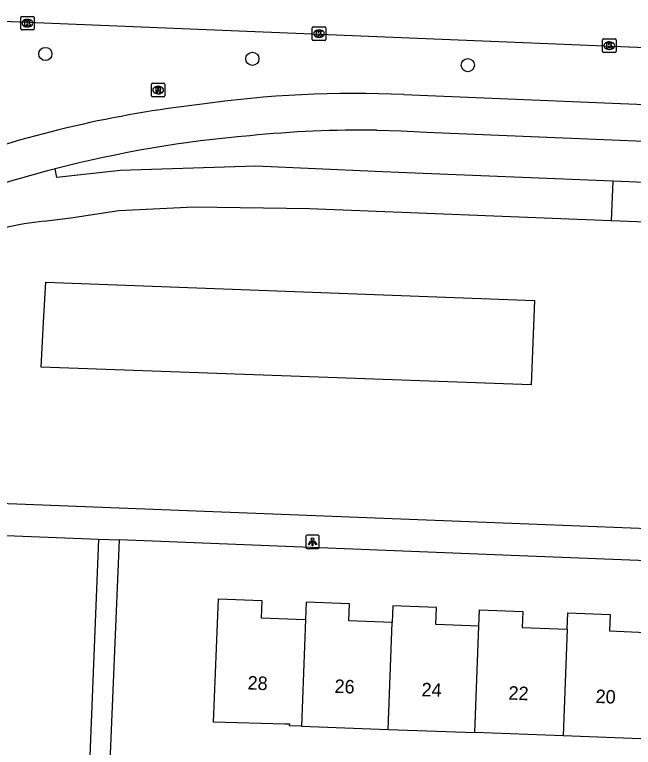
# Model space of a CAD drawing. Extents: x 161355 to 162026, y 386504 to 387459.
# Drawn here: x 161584 to 161629.9, y 387396.4 to 387450.8 of the extents above; entities that cross this region are included whole.
import ezdxf

# ---------------------------------------------------------------- set-up
doc = ezdxf.new("R2010")
doc.units = 0
for name, color, linetype in [('IMGEO_Boom', 7, 'Continuous'), ('IMGEO_Fietspad_gesloten', 7, 'Continuous'), ('IMGEO_Groenvoorziening', 7, 'Continuous'), ('IMGEO_Kolk', 7, 'Continuous'), ('IMGEO_Lichtpunt', 7, 'Continuous'), ('IMGEO_Pand', 7, 'Continuous'), ('IMGEO_Pand_nummerreeks', 7, 'Continuous'), ('IMGEO_Rijbaan_lokaal_gesloten', 7, 'Continuous'), ('IMGEO_Rioolput', 7, 'Continuous'), ('IMGEO_Voetpad_open', 7, 'Continuous')]:
    doc.layers.add(name, color=color, linetype=linetype)

msp = doc.modelspace()

# ---------------------------------------------------------------- linework, layer by layer
at = {"layer": 'IMGEO_Boom'}
for centre in [(161586.274, 387447.924), (161601.637, 387447.563), (161617.626, 387447.099)]:
    msp.add_circle(centre, 0.489, dxfattribs=at)
at = {"layer": 'IMGEO_Fietspad_gesloten'}
for points in [[(161612.89, 387444.91), (161652.822, 387443.267), (161706.244, 387441.015), (161723.243, 387440.365), (161738.753, 387439.947)], [(161610.883, 387442.256), (161612.683, 387442.214), (161614.558, 387442.129), (161644.429, 387440.874), (161676.294, 387439.535), (161679.83, 387439.386), (161708.067, 387438.213), (161738.649, 387436.943)], [(161586.996, 387439.386), (161586.923, 387439.367)]]:
    msp.add_lwpolyline(points, dxfattribs=at)
for centre, radius, start, end in [((161609.251, 387362.569), 82.421, 87.46975, 98.04602), ((161607.624, 387359.522), 85.235, 96.67591, 109.35439), ((161608.735, 387355.708), 86.455, 94.83564, 104.56317), ((161609.758, 387357.301), 84.963, 89.24122, 95.61351), ((161611.973, 387342.556), 100, 104.50687, 109.09324)]:
    msp.add_arc(centre, radius, start, end, dxfattribs=at)
at = {"layer": 'IMGEO_Groenvoorziening'}
msp.add_lwpolyline([(161622.32, 387423.351), (161585.965, 387424.664), (161586.147, 387428.006), (161586.309, 387430.965), (161622.577, 387429.606), (161622.32, 387423.351)], dxfattribs=at)
at = {"layer": 'IMGEO_Kolk'}
for p, q in [((161584.44, 387449.785), (161584.44, 387450.637)), ((161584.515, 387450.711), (161585.367, 387450.711)), ((161584.928, 387450.491), (161584.953, 387450.491)), ((161585.441, 387450.637), (161585.441, 387449.785)), ((161584.951, 387449.931), (161584.926, 387449.931)), ((161606.162, 387449.934), (161607.014, 387449.934)), ((161585.367, 387449.711), (161584.515, 387449.711)), ((161606.087, 387449.008), (161606.087, 387449.86)), ((161606.575, 387449.714), (161606.6, 387449.714)), ((161607.088, 387449.86), (161607.088, 387449.008)), ((161607.014, 387448.934), (161606.162, 387448.934)), ((161606.598, 387449.154), (161606.573, 387449.154)), ((161627.634, 387448.118), (161627.634, 387448.97)), ((161627.709, 387449.044), (161628.561, 387449.044)), ((161628.635, 387448.97), (161628.635, 387448.118)), ((161628.122, 387448.824), (161628.147, 387448.824)), ((161628.561, 387448.044), (161627.709, 387448.044)), ((161628.145, 387448.264), (161628.12, 387448.264))]:
    msp.add_line(p, q, dxfattribs=at)
for points in [[(161584.44, 387449.785), (161584.44, 387450.637)], [(161584.515, 387450.711), (161585.367, 387450.711)], [(161585.441, 387450.637), (161585.441, 387449.785)], [(161584.761, 387450.411), (161584.884, 387450.411), (161584.884, 387450.26), (161585.014, 387450.411), (161585.178, 387450.411), (161585.032, 387450.26), (161585.185, 387450.011), (161585.033, 387450.011), (161584.948, 387450.175), (161584.884, 387450.108), (161584.884, 387450.011), (161584.761, 387450.011), (161584.761, 387450.411)], [(161606.162, 387449.934), (161607.014, 387449.934)], [(161585.367, 387449.711), (161584.515, 387449.711)], [(161606.087, 387449.008), (161606.087, 387449.86)], [(161606.408, 387449.634), (161606.531, 387449.634), (161606.531, 387449.483), (161606.661, 387449.634), (161606.825, 387449.634), (161606.679, 387449.483), (161606.832, 387449.234), (161606.68, 387449.234), (161606.595, 387449.398), (161606.531, 387449.331), (161606.531, 387449.234), (161606.408, 387449.234), (161606.408, 387449.634)], [(161607.088, 387449.86), (161607.088, 387449.008)], [(161607.014, 387448.934), (161606.162, 387448.934)], [(161627.634, 387448.118), (161627.634, 387448.97)], [(161627.709, 387449.044), (161628.561, 387449.044)], [(161628.635, 387448.97), (161628.635, 387448.118)], [(161627.955, 387448.744), (161628.078, 387448.744), (161628.078, 387448.593), (161628.208, 387448.744), (161628.372, 387448.744), (161628.226, 387448.593), (161628.379, 387448.344), (161628.227, 387448.344), (161628.142, 387448.508), (161628.078, 387448.441), (161628.078, 387448.344), (161627.955, 387448.344), (161627.955, 387448.744)], [(161628.561, 387448.044), (161627.709, 387448.044)]]:
    msp.add_lwpolyline(points, dxfattribs=at)
for centre, start, end in [((161584.517, 387450.635), 91.552, 178.448), ((161584.517, 387450.635), 91.552, 178.448), ((161585.365, 387450.635), 1.552, 88.448), ((161585.365, 387450.635), 1.552, 88.448), ((161606.164, 387449.858), 91.552, 178.448), ((161606.164, 387449.858), 91.552, 178.448), ((161607.012, 387449.858), 1.552, 88.448), ((161607.012, 387449.858), 1.552, 88.448), ((161584.517, 387449.787), 181.552, 268.448), ((161584.517, 387449.787), 181.552, 268.448), ((161585.365, 387449.787), 271.552, 358.448), ((161585.365, 387449.787), 271.552, 358.448), ((161606.164, 387449.01), 181.552, 268.448), ((161606.164, 387449.01), 181.552, 268.448), ((161607.012, 387449.01), 271.552, 358.448), ((161607.012, 387449.01), 271.552, 358.448), ((161627.711, 387448.968), 91.552, 178.448), ((161627.711, 387448.968), 91.552, 178.448), ((161628.559, 387448.968), 1.552, 88.448), ((161628.559, 387448.968), 1.552, 88.448), ((161627.711, 387448.12), 181.552, 268.448), ((161627.711, 387448.12), 181.552, 268.448), ((161628.559, 387448.12), 271.552, 358.448), ((161628.559, 387448.12), 271.552, 358.448)]:
    msp.add_arc(centre, 0.0765, start, end, dxfattribs=at)
for centre, major_axis, ratio, start_param, end_param in [((161584.927, 387450.211), (-0.387, 0.002), 0.722429, 4.712389, 7.853982), ((161584.952, 387450.211), (-0.39, 0.002), 0.717154, 1.570796, 4.712389), ((161606.574, 387449.434), (-0.387, 0.002), 0.722429, 4.712389, 7.853982), ((161606.599, 387449.434), (-0.39, 0.002), 0.717154, 1.570796, 4.712389), ((161628.121, 387448.544), (-0.387, 0.002), 0.722429, 4.712389, 7.853982), ((161628.146, 387448.544), (-0.39, 0.002), 0.717154, 1.570796, 4.712389)]:
    msp.add_ellipse(centre, major_axis=major_axis, ratio=ratio, start_param=start_param, end_param=end_param, dxfattribs=at)
at = {"layer": 'IMGEO_Lichtpunt'}
for p, q in [((161605.608, 387412.101), (161605.608, 387411.294)), ((161605.608, 387412.101), (161605.608, 387411.294)), ((161606.51, 387412.196), (161605.702, 387412.196)), ((161606.51, 387412.196), (161605.702, 387412.196)), ((161606.604, 387411.294), (161606.604, 387412.101)), ((161606.604, 387411.294), (161606.604, 387412.101)), ((161605.702, 387411.2), (161606.51, 387411.2)), ((161605.702, 387411.2), (161606.51, 387411.2))]:
    msp.add_line(p, q, dxfattribs=at)
for points in [[(161605.982, 387411.765), (161606.021, 387411.737), (161605.833, 387411.475), (161605.795, 387411.502), (161605.982, 387411.765)], [(161606.084, 387411.717), (161606.131, 387411.717), (161606.131, 387411.395), (161606.084, 387411.395), (161606.084, 387411.717)], [(161606.194, 387411.737), (161606.232, 387411.764), (161606.419, 387411.502), (161606.38, 387411.474), (161606.194, 387411.737)]]:
    msp.add_lwpolyline(points, dxfattribs=at)
msp.add_circle((161606.107, 387411.899), 0.0994, dxfattribs=at)
for centre, start, end in [((161605.702, 387412.101), 90, 180), ((161605.702, 387412.101), 90, 180), ((161606.51, 387412.101), 0, 90), ((161606.51, 387412.101), 0, 90), ((161605.702, 387411.294), 180, 270), ((161605.702, 387411.294), 180, 270), ((161606.51, 387411.294), 270, 0), ((161606.51, 387411.294), 270, 360)]:
    msp.add_arc(centre, 0.0946, start, end, dxfattribs=at)
at = {"layer": 'IMGEO_Pand'}
for points in [[(161605.28, 387398.002), (161604.405, 387398.035), (161604.409, 387398.144), (161604.067, 387398.158), (161598.764, 387398.304), (161599.13, 387407.465), (161602.333, 387407.337), (161602.282, 387406.055), (161605.577, 387405.923)], [(161612.015, 387405.692), (161608.789, 387405.82), (161608.839, 387407.078), (161605.628, 387407.206), (161605.577, 387405.923)], [(161618.456, 387405.423), (161615.246, 387405.552), (161615.296, 387406.804), (161612.063, 387406.933), (161612.039, 387406.328), (161612.015, 387405.692)], [(161618.456, 387405.423), (161618.505, 387406.64), (161621.712, 387406.512), (161621.665, 387405.335), (161625.002, 387405.202)], [(161625.002, 387405.202), (161625.051, 387406.425), (161628.201, 387406.299), (161628.152, 387405.07), (161631.41, 387404.94)], [(161605.577, 387405.923), (161605.28, 387398.002)], [(161611.72, 387397.762), (161612.015, 387405.692)], [(161618.16, 387397.522), (161618.456, 387405.423)], [(161625.002, 387405.202), (161624.705, 387397.278)], [(161605.28, 387398.002), (161611.72, 387397.762)], [(161611.72, 387397.762), (161618.16, 387397.522)], [(161624.705, 387397.278), (161618.16, 387397.522)], [(161631.116, 387397.04), (161624.705, 387397.278)]]:
    msp.add_lwpolyline(points, dxfattribs=at)
at = {"layer": 'IMGEO_Rijbaan_lokaal_gesloten'}
msp.add_lwpolyline([(161566.731, 387450.192), (161568.939, 387450.72), (161570.123, 387450.845), (161577.085, 387450.606), (161735.771, 387444.103), (161739.669, 387443.941)], dxfattribs=at)
at = {"layer": 'IMGEO_Rioolput'}
for p, q in [((161594.145, 387444.82), (161594.145, 387445.672)), ((161594.22, 387445.746), (161595.072, 387445.746)), ((161595.146, 387445.672), (161595.146, 387444.82)), ((161594.633, 387445.526), (161594.658, 387445.526)), ((161595.072, 387444.746), (161594.22, 387444.746)), ((161594.656, 387444.966), (161594.631, 387444.966))]:
    msp.add_line(p, q, dxfattribs=at)
for points in [[(161594.145, 387444.82), (161594.145, 387445.672)], [(161594.22, 387445.746), (161595.072, 387445.746)], [(161595.146, 387445.672), (161595.146, 387444.82)], [(161594.734, 387445.444), (161594.482, 387445.446), (161594.482, 387445.046)], [(161594.482, 387445.046), (161594.606, 387445.046), (161594.606, 387445.208), (161594.617, 387445.208)], [(161594.66, 387445.365), (161594.606, 387445.365), (161594.606, 387445.284)], [(161594.606, 387445.284), (161594.658, 387445.284)], [(161594.664, 387445.179), (161594.735, 387445.046), (161594.875, 387445.046), (161594.81, 387445.172)], [(161595.072, 387444.746), (161594.22, 387444.746)]]:
    msp.add_lwpolyline(points, dxfattribs=at)
for centre, radius, start, end in [((161594.222, 387445.67), 0.0765, 91.552, 178.448), ((161594.222, 387445.67), 0.0765, 91.552, 178.448), ((161595.07, 387445.67), 0.0765, 1.552, 88.448), ((161595.07, 387445.67), 0.0765, 1.552, 88.448), ((161594.616, 387445.155), 0.0533, 26.0293, 88.6989), ((161594.642, 387445.473), 0.19, 274.7715, 282.9687), ((161594.666, 387445.269), 0.0964, 77.0061, 93.1865), ((161594.68, 387445.326), 0.0378, 276.6634, 79.6772), ((161594.733, 387445.334), 0.109, 350.3612, 89.416), ((161594.731, 387445.334), 0.112, 277.5842, 350.9817), ((161594.715, 387445.119), 0.108, 29.5134, 73.7905), ((161594.222, 387444.822), 0.0765, 181.552, 268.448), ((161594.222, 387444.822), 0.0765, 181.552, 268.448), ((161595.07, 387444.822), 0.0765, 271.552, 358.448), ((161595.07, 387444.822), 0.0765, 271.552, 358.448)]:
    msp.add_arc(centre, radius, start, end, dxfattribs=at)
for centre, major_axis, ratio, start_param, end_param in [((161594.632, 387445.246), (-0.387, 0.002), 0.722429, 4.712389, 7.853982), ((161594.657, 387445.246), (-0.39, 0.002), 0.717154, 1.570796, 4.712389)]:
    msp.add_ellipse(centre, major_axis=major_axis, ratio=ratio, start_param=start_param, end_param=end_param, dxfattribs=at)
at = {"layer": 'IMGEO_Voetpad_open'}
for points in [[(161628.393, 387438.471), (161612.483, 387439.13), (161610.753, 387439.197), (161601.898, 387439.584), (161591.835, 387439.274), (161587.121, 387438.74), (161586.996, 387439.386)], [(161628.393, 387438.471), (161628.278, 387435.565)], [(161739.77, 387436.897), (161739.654, 387433.94), (161736.908, 387434.048), (161707.941, 387435.177), (161676.122, 387436.495), (161644.302, 387437.813), (161628.393, 387438.471)], [(161586.184, 387435.51), (161588.172, 387435.749), (161591.723, 387436.289), (161597.309, 387436.57), (161605.878, 387436.445), (161628.278, 387435.565)], [(161628.278, 387435.565), (161651.455, 387434.654), (161651.548, 387434.648)], [(161652.45, 387411.813), (161622.17, 387413.001), (161531.548, 387416.555)], [(161531.527, 387414.224), (161590.228, 387411.885)], [(161590.228, 387411.885), (161589.287, 387388.381)], [(161590.228, 387411.885), (161591.757, 387411.83)], [(161591.757, 387411.83), (161590.756, 387388.297)], [(161652.397, 387409.433), (161622.077, 387410.632), (161591.757, 387411.83)]]:
    msp.add_lwpolyline(points, dxfattribs=at)
msp.add_arc((161589.025, 387410.297), 25.373, 96.4297, 110.0753, dxfattribs=at)

# ---------------------------------------------------------------- texts
at = {"layer": 'IMGEO_Pand_nummerreeks'}
for s, rotation, p in [('28', 357.7789, (161601.268, 387400.729)), ('26', 357.7769, (161607.723, 387400.478)), ('24', 357.7769, (161614.181, 387400.228)), ('22', 357.7789, (161620.636, 387399.977)), ('20', 357.7789, (161627.1, 387399.727))]:
    msp.add_text(s, height=1, rotation=rotation, dxfattribs=at).set_placement(p)

doc.saveas('drawing.dxf')
